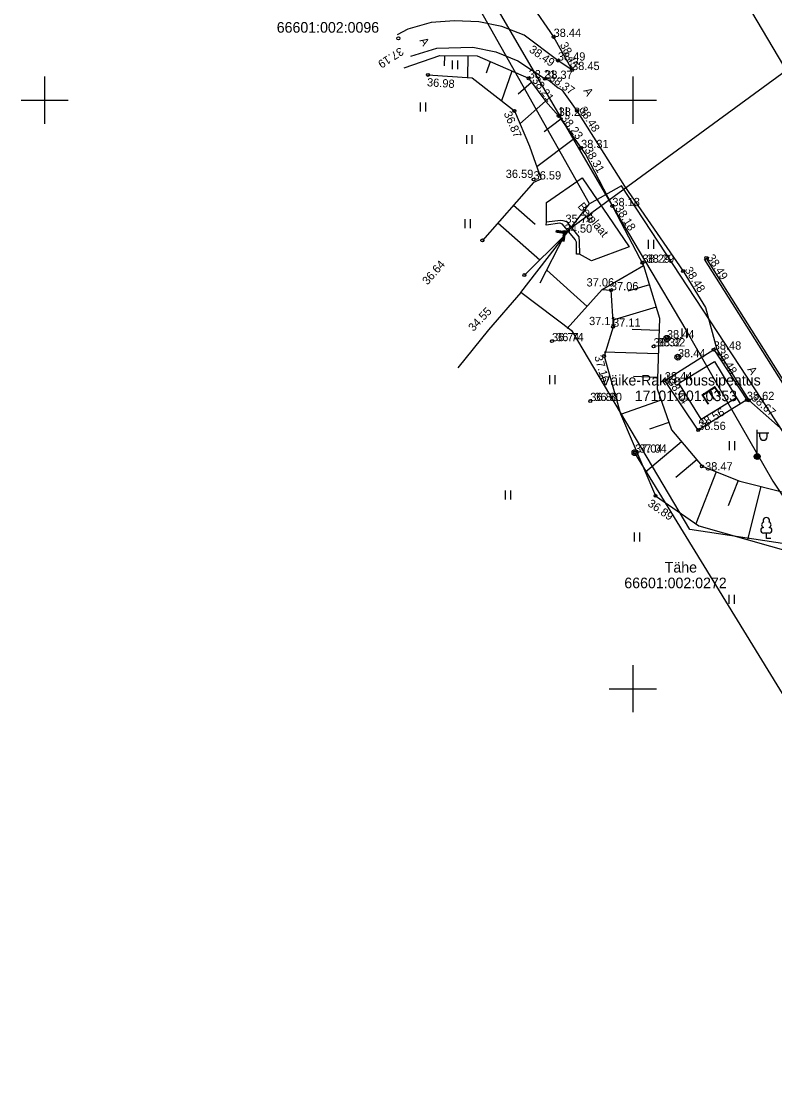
# Model space of a CAD drawing. Extents: x 627548 to 628052, y 6467984 to 6468802.
# Drawn here: x 627598 to 627662.1, y 6468617.2 to 6468706.7 of the extents above; entities that cross this region are included whole.
import ezdxf

# ---------------------------------------------------------------- set-up
doc = ezdxf.new("R2010")
doc.units = 0
for name, color, linetype in [('HALJASTUS', 7, 'Continuous'), ('HOONE', 7, 'Continuous'), ('KORGUS-EH2000', 7, 'Continuous'), ('MOOTKORG-EH2000', 7, 'Continuous'), ('MOOTKORGMUU-EH2000', 7, 'Continuous'), ('MOOTMPUNKT', 7, 'Continuous'), ('MPOHULIIN', 7, 'Continuous'), ('PIIR', 7, 'Continuous'), ('POST', 7, 'Continuous'), ('PUU', 7, 'Continuous'), ('RAJATIS', 7, 'Continuous'), ('RELJEEF', 7, 'Continuous'), ('SITRASS', 7, 'Continuous'), ('TEE', 7, 'Continuous'), ('TRUUP', 7, 'Continuous'), ('VORK', 7, 'Continuous')]:
    doc.layers.add(name, color=color, linetype=linetype)

msp = doc.modelspace()

# ---------------------------------------------------------------- linework, layer by layer
at = {"layer": 'HALJASTUS'}
for p, q in [((627634.652, 6468703.386), (627634.652, 6468702.625)), ((627635.107, 6468703.386), (627635.107, 6468702.625)), ((627631.915, 6468699.814), (627631.915, 6468699.053)), ((627632.37, 6468699.814), (627632.37, 6468699.053)), ((627643.881, 6468699.403), (627643.881, 6468698.642)), ((627644.336, 6468699.403), (627644.336, 6468698.642)), ((627635.87, 6468697.043), (627635.87, 6468696.282)), ((627636.325, 6468697.043), (627636.325, 6468696.282)), ((627635.709, 6468689.887), (627635.709, 6468689.126)), ((627636.164, 6468689.887), (627636.164, 6468689.126)), ((627651.298, 6468688.126), (627651.298, 6468687.365)), ((627651.753, 6468688.126), (627651.753, 6468687.365)), ((627654.178, 6468680.605), (627654.178, 6468679.844)), ((627654.633, 6468680.605), (627654.633, 6468679.844)), ((627642.93, 6468676.632), (627642.93, 6468675.871)), ((627643.385, 6468676.632), (627643.385, 6468675.871)), ((627658.188, 6468671.041), (627658.188, 6468670.28)), ((627658.643, 6468671.041), (627658.643, 6468670.28)), ((627639.149, 6468666.837), (627639.149, 6468666.076)), ((627639.604, 6468666.837), (627639.604, 6468666.076)), ((627650.107, 6468663.271), (627650.107, 6468662.51)), ((627650.562, 6468663.271), (627650.562, 6468662.51)), ((627658.16, 6468657.97), (627658.16, 6468657.209)), ((627658.615, 6468657.97), (627658.615, 6468657.209))]:
    msp.add_line(p, q, dxfattribs=at)
at = {"layer": 'HOONE'}
for points in [[(627653.91, 6468675.948), (627656.938, 6468677.796)], [(627656.938, 6468677.796), (627659.134, 6468674.215)], [(627655.806, 6468672.914), (627653.91, 6468675.948)], [(627655.806, 6468672.914), (627658.806, 6468674.749)]]:
    msp.add_lwpolyline(points, dxfattribs=at)
at = {"layer": 'KORGUS-EH2000'}
for centre in [(627630.07, 6468705.257), (627632.58, 6468702.147), (627639.93, 6468699.087), (627645.25, 6468699.097), (627637.21, 6468688.087), (627656.24, 6468686.597), (627640.79, 6468685.147), (627654.27, 6468685.487), (627647.56, 6468678.267), (627659.85, 6468674.507), (627655.88, 6468668.897), (627651.93, 6468666.397)]:
    msp.add_circle(centre, 0.125, dxfattribs=at)
at = {"layer": 'MOOTMPUNKT'}
for centre in [(627643.266, 6468705.375), (627643.625, 6468703.365), (627644.837, 6468702.56), (627641.143, 6468701.858), (627642.546, 6468701.813), (627643.694, 6468698.663), (627645.603, 6468695.932), (627641.563, 6468693.265), (627648.26, 6468691.002), (627644.183, 6468688.808), (627644.203, 6468688.747), (627650.82, 6468686.187), (627648.135, 6468683.852), (627648.322, 6468680.758), (627652.896, 6468679.773), (627643.128, 6468679.527), (627651.767, 6468679.083), (627653.833, 6468678.163), (627656.874, 6468678.811), (627652.718, 6468676.196), (627646.383, 6468674.441), (627659.691, 6468674.531), (627655.556, 6468671.981), (627650.185, 6468670.056)]:
    msp.add_circle(centre, 0.125, dxfattribs=at)
at = {"layer": 'MPOHULIIN'}
msp.add_lwpolyline([(627673.058, 6468632.736), (627650.185, 6468670.056)], dxfattribs=at)
at = {"layer": 'PIIR'}
for p, q in [((627646.31, 6468691.19), (627629.12, 6468721.76)), ((627649.05, 6468692.73), (627646.31, 6468691.19)), ((627667.34, 6468664.86), (627649.05, 6468692.73)), ((627640.48, 6468683.65), (627646.31, 6468691.19)), ((627640.48, 6468683.65), (627637.73, 6468680.5)), ((627644.86, 6468680.34), (627640.48, 6468683.65)), ((627637.73, 6468680.5), (627635.118, 6468677.272)), ((627654.85, 6468663.52), (627644.86, 6468680.34)), ((627663.66, 6468662.2), (627654.85, 6468663.52))]:
    msp.add_line(p, q, dxfattribs=at)
at = {"layer": 'POST'}
for p, q in [((627660.575, 6468669.985), (627660.575, 6468671.985)), ((627660.575, 6468671.735), (627661.575, 6468671.735)), ((627660.802, 6468671.414), (627660.802, 6468671.735)), ((627661.414, 6468671.414), (627661.414, 6468671.735))]:
    msp.add_line(p, q, dxfattribs=at)
for centre, radius in [((627650.185, 6468670.056), 0.25), ((627650.185, 6468670.056), 0.0234), ((627660.575, 6468669.735), 0.25), ((627660.575, 6468669.735), 0.225), ((627660.575, 6468669.735), 0.2), ((627660.575, 6468669.735), 0.175), ((627660.575, 6468669.735), 0.15), ((627660.575, 6468669.735), 0.125), ((627660.575, 6468669.735), 0.1), ((627660.575, 6468669.735), 0.075), ((627660.575, 6468669.735), 0.05), ((627660.575, 6468669.735), 0.025)]:
    msp.add_circle(centre, radius, dxfattribs=at)
msp.add_arc((627661.108, 6468671.414), 0.306, 180, 0, dxfattribs=at)
at = {"layer": 'PUU'}
for p, q in [((627661.591, 6468663.227), (627661.111, 6468663.227)), ((627661.351, 6468662.752), (627661.351, 6468663.227)), ((627661.731, 6468662.752), (627661.351, 6468662.752))]:
    msp.add_line(p, q, dxfattribs=at)
for centre, radius, start, end in [((627661.181, 6468663.925), 0.233, 109.02174, 253.14154), ((627661.351, 6468664.272), 0.277, 332.5799, 207.4201), ((627661.521, 6468663.925), 0.233, 286.85082, 70.98591), ((627661.113, 6468663.465), 0.238, 90.0016, 269.3953), ((627661.588, 6468663.465), 0.238, 270.6047, 89.9984)]:
    msp.add_arc(centre, radius, start, end, dxfattribs=at)
at = {"layer": 'RAJATIS'}
for centre in [(627652.896, 6468679.773), (627653.833, 6468678.163)]:
    msp.add_circle(centre, 0.25, dxfattribs=at)
at = {"layer": 'RELJEEF'}
for p, q in [((627633.982, 6468703.788), (627633.972, 6468702.921)), ((627635.982, 6468703.765), (627635.96, 6468701.926)), ((627637.885, 6468703.275), (627637.54, 6468702.301)), ((627639.723, 6468702.475), (627638.828, 6468699.949)), ((627641.395, 6468701.517), (627640.256, 6468700.516)), ((627642.589, 6468699.904), (627640.407, 6468697.986)), ((627643.892, 6468698.381), (627642.462, 6468697.305)), ((627645.04, 6468696.742), (627641.835, 6468694.33)), ((627639.855, 6468691.088), (627641.695, 6468689.467)), ((627638.533, 6468689.587), (627642.105, 6468686.441)), ((627646.115, 6468682.484), (627642.681, 6468685.552)), ((627651.409, 6468684.325), (627649.586, 6468683.784)), ((627651.978, 6468682.408), (627648.289, 6468681.312)), ((627652.224, 6468680.448), (627649.939, 6468680.519)), ((627652.162, 6468678.449), (627647.57, 6468678.592)), ((627652.101, 6468676.45), (627650.067, 6468676.513)), ((627652.414, 6468674.509), (627648.961, 6468673.305)), ((627653.072, 6468672.62), (627651.412, 6468672.042)), ((627654.148, 6468670.969), (627651.071, 6468668.394)), ((627655.431, 6468669.435), (627653.663, 6468667.955)), ((627657.089, 6468668.42), (627655.356, 6468664.022)), ((627658.95, 6468667.687), (627658.101, 6468665.532)), ((627660.884, 6468667.18), (627659.752, 6468662.67))]:
    msp.add_line(p, q, dxfattribs=at)
for points in [[(627630.555, 6468702.745), (627633.602, 6468703.792), (627636.779, 6468703.755), (627641.143, 6468701.858), (627642.594, 6468699.898), (627643.694, 6468698.663), (627646.012, 6468695.356), (627648.98, 6468689.647), (627650.921, 6468685.967), (627652.256, 6468681.471), (627652.071, 6468675.492), (627653.291, 6468671.992), (627655.882, 6468668.896), (627659.102, 6468667.627), (627663.024, 6468666.643), (627670.269, 6468662.476), (627683.816, 6468643.643), (627687.532, 6468638.292), (627690.387, 6468634.82), (627689.443, 6468632.589), (627686.057, 6468631.231), (627679.021, 6468629.928)], [(627632.581, 6468702.143), (627636.331, 6468701.902), (627639.934, 6468699.084), (627641.228, 6468696.081), (627642.198, 6468693.28)], [(627642.198, 6468693.28), (627641.555, 6468693.017), (627637.211, 6468688.086)], [(627640.788, 6468685.148), (627644.203, 6468688.5)], [(627642.129, 6468684.482), (627644.203, 6468688.5)], [(627644.426, 6468680.593), (627647.397, 6468683.918), (627650.921, 6468685.967)], [(627647.397, 6468683.918), (627648.135, 6468683.852), (627648.322, 6468680.758), (627647.557, 6468678.266), (627648.942, 6468673.349), (627651.927, 6468666.4), (627655.621, 6468663.838), (627665.909, 6468660.929), (627669.195, 6468655.778), (627677.582, 6468646.082), (627685.387, 6468632.394), (627678.61, 6468631.426)]]:
    msp.add_lwpolyline(points, dxfattribs=at)
at = {"layer": 'SITRASS'}
msp.add_lwpolyline([(627601.95, 6468775.665), (627611.516, 6468756.586), (627616.834, 6468745.298), (627619.184, 6468741.186), (627623.567, 6468733.678), (627630.719, 6468721.267), (627637.953, 6468708.68), (627647.64, 6468692.032), (627654.507, 6468680.481), (627661.905, 6468667.643), (627667.084, 6468659.838), (627674.129, 6468649.944), (627689.767, 6468629.543), (627695.628, 6468619.665), (627699.564, 6468614.681), (627710.374, 6468599.048), (627720.659, 6468583.91), (627729.18, 6468571.423), (627736.574, 6468559.697), (627746.582, 6468544.707), (627757.269, 6468529.067), (627768.1, 6468513.354)], dxfattribs=at)
at = {"layer": 'TEE'}
for points in [[(627700.939, 6468658.86), (627696.392, 6468656.072), (627693.013, 6468655.978), (627687.872, 6468663.274), (627673.734, 6468684.205), (627667.271, 6468695.423), (627655.655, 6468715.038), (627640.744, 6468741.218), (627629.668, 6468761.293)], [(627621.813, 6468712.448), (627624.169, 6468713.467), (627629.552, 6468714.398), (627633.52, 6468713.753), (627635.3, 6468713.094), (627639.562, 6468710.382), (627641.314, 6468708.212), (627643.266, 6468705.375), (627644.837, 6468702.56), (627643.625, 6468703.365), (627640.773, 6468705.527), (627638.868, 6468706.251), (627636.924, 6468706.658), (627634.856, 6468706.73), (627632.859, 6468706.587), (627630.866, 6468706.032), (627629.956, 6468705.539)], [(627631.134, 6468703.73), (627633.346, 6468704.427), (627636.399, 6468704.497), (627638.36, 6468704.107), (627640.222, 6468703.346), (627642.546, 6468701.813), (627642.851, 6468701.697)], [(627642.851, 6468701.697), (627643.652, 6468701.039), (627643.972, 6468700.891), (627645.246, 6468699.098), (627649.286, 6468692.707), (627654.27, 6468685.483), (627656.176, 6468682.398), (627657.145, 6468678.821), (627659.852, 6468674.505), (627663.528, 6468671.281), (627666.594, 6468668.111), (627670.77, 6468663.802), (627676.196, 6468657.041), (627682.033, 6468649.275), (627691.556, 6468636.216), (627691.146, 6468633.38), (627690.377, 6468632.362), (627683.705, 6468630.285), (627675.534, 6468628.326)], [(627642.652, 6468689.68), (627642.654, 6468691.306), (627645.699, 6468693.406), (627649.693, 6468687.545), (627646.502, 6468686.358), (627645.468, 6468686.925)], [(627656.072, 6468686.492), (627666.322, 6468670.277), (627666.512, 6468670.325)], [(627666.512, 6468670.325), (627656.241, 6468686.596)], [(627655.556, 6468671.981), (627652.718, 6468676.196), (627656.874, 6468678.811), (627659.691, 6468674.531), (627655.556, 6468671.981)]]:
    msp.add_lwpolyline(points, dxfattribs=at)
at = {"layer": 'TRUUP'}
for p, q in [((627643.493, 6468688.782), (627643.515, 6468688.923)), ((627643.499, 6468688.782), (627643.591, 6468688.912)), ((627643.5, 6468688.826), (627643.563, 6468688.916)), ((627644.203, 6468688.747), (627643.504, 6468688.853)), ((627643.508, 6468688.881), (627643.536, 6468688.92)), ((627644.284, 6468688.807), (627643.515, 6468688.923)), ((627643.526, 6468688.777), (627643.619, 6468688.907)), ((627643.554, 6468688.773), (627643.646, 6468688.903)), ((627643.582, 6468688.769), (627643.674, 6468688.899)), ((627643.609, 6468688.765), (627643.702, 6468688.895)), ((627643.637, 6468688.761), (627643.729, 6468688.891)), ((627643.665, 6468688.756), (627643.757, 6468688.887)), ((627643.692, 6468688.752), (627643.785, 6468688.882)), ((627643.72, 6468688.748), (627643.812, 6468688.878)), ((627643.748, 6468688.744), (627643.84, 6468688.874)), ((627643.775, 6468688.74), (627643.868, 6468688.87)), ((627643.803, 6468688.736), (627643.895, 6468688.866)), ((627643.831, 6468688.731), (627643.923, 6468688.861)), ((627643.859, 6468688.727), (627643.951, 6468688.857)), ((627643.886, 6468688.723), (627643.978, 6468688.853)), ((627643.914, 6468688.719), (627644.006, 6468688.849)), ((627643.942, 6468688.715), (627644.034, 6468688.845)), ((627643.969, 6468688.71), (627644.061, 6468688.84)), ((627643.997, 6468688.706), (627644.089, 6468688.836)), ((627644.025, 6468688.702), (627644.117, 6468688.832)), ((627644.052, 6468688.698), (627644.145, 6468688.828)), ((627644.122, 6468688.687), (627643.493, 6468688.782)), ((627644.027, 6468688.059), (627644.122, 6468688.687)), ((627644.027, 6468688.059), (627644.168, 6468688.037)), ((627644.028, 6468688.058), (627644.21, 6468688.315)), ((627644.035, 6468688.111), (627644.218, 6468688.369)), ((627644.043, 6468688.166), (627644.226, 6468688.424)), ((627644.051, 6468688.221), (627644.234, 6468688.479)), ((627644.055, 6468688.054), (627644.201, 6468688.26)), ((627644.06, 6468688.276), (627644.243, 6468688.534)), ((627644.068, 6468688.331), (627644.251, 6468688.589)), ((627644.076, 6468688.386), (627644.259, 6468688.644)), ((627644.08, 6468688.694), (627644.172, 6468688.824)), ((627644.083, 6468688.05), (627644.193, 6468688.205)), ((627644.085, 6468688.441), (627644.268, 6468688.699)), ((627644.093, 6468688.496), (627644.276, 6468688.754)), ((627644.097, 6468688.048), (627644.203, 6468688.747)), ((627644.101, 6468688.551), (627644.283, 6468688.807)), ((627644.108, 6468688.689), (627644.2, 6468688.819)), ((627644.11, 6468688.606), (627644.255, 6468688.811)), ((627644.111, 6468688.046), (627644.185, 6468688.15)), ((627644.118, 6468688.661), (627644.228, 6468688.815)), ((627644.139, 6468688.042), (627644.176, 6468688.095)), ((627644.168, 6468688.037), (627644.284, 6468688.807))]:
    msp.add_line(p, q, dxfattribs=at)
for points in [[(627644.203, 6468688.747), (627667.616, 6468705.898)], [(627642.652, 6468689.68), (627643.865, 6468689.797), (627644.045, 6468689.793), (627644.356, 6468689.699), (627645.415, 6468688.393), (627645.443, 6468687.956), (627645.468, 6468686.925), (627645.199, 6468686.922), (627645.222, 6468687.927), (627645.092, 6468688.175), (627644.017, 6468689.469), (627643.808, 6468689.539), (627642.621, 6468689.374), (627642.652, 6468689.68)]]:
    msp.add_lwpolyline(points, dxfattribs=at)
at = {"layer": 'VORK'}
for p, q in [((627600, 6468702), (627600, 6468698)), ((627650, 6468702), (627650, 6468698)), ((627598, 6468700), (627602, 6468700)), ((627648, 6468700), (627652, 6468700)), ((627650, 6468652), (627650, 6468648)), ((627648, 6468650), (627652, 6468650))]:
    msp.add_line(p, q, dxfattribs=at)

# ---------------------------------------------------------------- texts
at = {"layer": 'HOONE'}
msp.add_text('E', height=1.4, rotation=303.1447, dxfattribs=at).set_placement((627655.73, 6468675.103))
at = {"layer": 'KORGUS-EH2000'}
for s, rotation, p in [('38.45', 297.38275, (627643.779, 6468704.717)), (' 37.19', 212.83747, (627630.449, 6468704.671)), ('38.49', 325.1527, (627641.127, 6468704.152)), (' 36.98', 356.32285, (627632.231, 6468701.201)), ('38.21', 306.45913, (627641.4, 6468701.683)), ('38.37', 324.983, (627642.83, 6468701.767)), (' 36.87', 293.31133, (627638.908, 6468699.116)), ('38.23', 307.49333, (627643.851, 6468698.45)), (' 38.48', 302.29857, (627645.262, 6468699.417)), ('38.31', 299.517, (627645.875, 6468695.791)), ('38.18', 301.66198, (627648.469, 6468690.819)), (' 36.64', 48.62133, (627632.377, 6468684.065)), (' 38.49', 302.262, (627656.155, 6468686.859)), (' 38.48', 301.70894, (627654.243, 6468685.807)), (' 34.55', 46.48002, (627636.267, 6468680.118)), (' 37.16', 285.73124, (627646.652, 6468678.466)), ('38.48', 300.95132, (627657.109, 6468678.636)), ('38.44', 303.21192, (627652.953, 6468676.064)), (' 38.67', 318.74793, (627659.808, 6468674.798)), ('38.56', 30.91636, (627655.866, 6468672.111)), (' 36.89', 325.25648, (627650.996, 6468665.734))]:
    msp.add_text(s, height=0.7, rotation=rotation, dxfattribs=at).set_placement(p)
for s, p in [('36.59', (627639.2, 6468693.395)), ('38.29', (627651.17, 6468686.187)), ('37.06', (627646.068, 6468684.177)), ('37.11', (627646.279, 6468680.894)), ('36.74', (627643.478, 6468679.527)), ('38.32', (627652.117, 6468679.083)), ('36.80', (627646.733, 6468674.441)), ('37.04', (627650.535, 6468670.056)), (' 38.47', (627655.882, 6468668.546))]:
    msp.add_text(s, height=0.7, dxfattribs=at).set_placement(p)
at = {"layer": 'MOOTKORG-EH2000'}
for s, p in [('38.44', (627643.266, 6468705.375)), ('38.49', (627643.625, 6468703.365)), ('38.45', (627644.837, 6468702.56)), ('38.21', (627641.143, 6468701.858)), ('38.37', (627642.546, 6468701.813)), ('38.23', (627643.694, 6468698.663)), ('38.31', (627645.603, 6468695.932)), ('36.59', (627641.563, 6468693.265)), ('38.18', (627648.26, 6468691.002)), ('34.50', (627644.203, 6468688.747)), ('38.29', (627650.82, 6468686.187)), ('37.06', (627648.135, 6468683.852)), ('37.11', (627648.322, 6468680.758)), ('36.74', (627643.128, 6468679.527)), ('38.44', (627652.896, 6468679.773)), ('38.32', (627651.767, 6468679.083)), ('38.48', (627656.874, 6468678.811)), ('38.44', (627653.833, 6468678.163)), ('38.44', (627652.718, 6468676.196)), ('36.80', (627646.383, 6468674.441)), ('38.62', (627659.691, 6468674.531)), ('38.56', (627655.556, 6468671.981)), ('37.04', (627650.185, 6468670.056))]:
    msp.add_text(s, height=0.7, dxfattribs=at).set_placement(p)
at = {"layer": 'MOOTKORGMUU-EH2000'}
msp.add_text('35.76', height=0.7, dxfattribs=at).set_placement((627644.274, 6468689.58))
at = {"layer": 'PIIR'}
for s, p in [('66601:002:0096', (627619.733, 6468705.735)), ('Väike-Rakke bussipeatus', (627647.291, 6468675.764)), ('17101:001:0353', (627650.16, 6468674.433)), ('Tähe', (627652.713, 6468659.871)), ('66601:002:0272', (627649.278, 6468658.54))]:
    msp.add_text(s, height=0.9, dxfattribs=at).set_placement(p)
at = {"layer": 'TEE'}
for s, rotation, p in [('A', 302.18787, (627631.842, 6468705.067)), ('A', 302.18787, (627645.772, 6468700.802)), ('Betplaat', 309.24742, (627645.271, 6468690.967)), ('A', 302.18787, (627659.712, 6468677.123))]:
    msp.add_text(s, height=0.7, rotation=rotation, dxfattribs=at).set_placement(p)

doc.saveas('drawing.dxf')
